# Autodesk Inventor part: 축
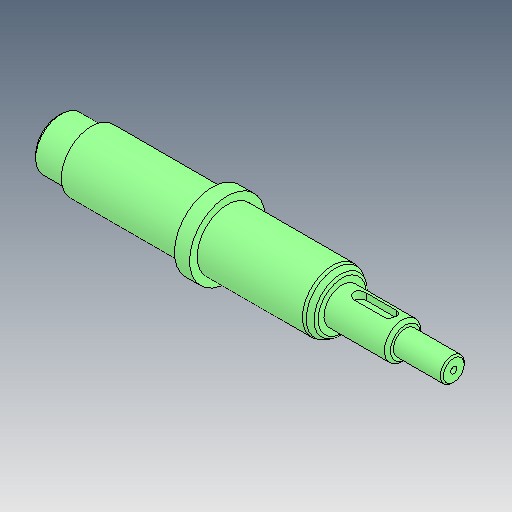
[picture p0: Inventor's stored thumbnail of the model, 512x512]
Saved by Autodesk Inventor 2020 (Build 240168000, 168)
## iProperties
Created: 2024-11
Part Number: 축
Material: 강철, 탄소
Document SubType Name: Modeling
Designer: shin
Density: 7.85 g/cm^3
Appearance: 기본값
Author: jhkim
Sending System: Autodesk Inventor 2025
Preprocessor: ST-DEVELOPER v20
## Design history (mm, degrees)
feature "솔리드1"
node "솔리드2"
